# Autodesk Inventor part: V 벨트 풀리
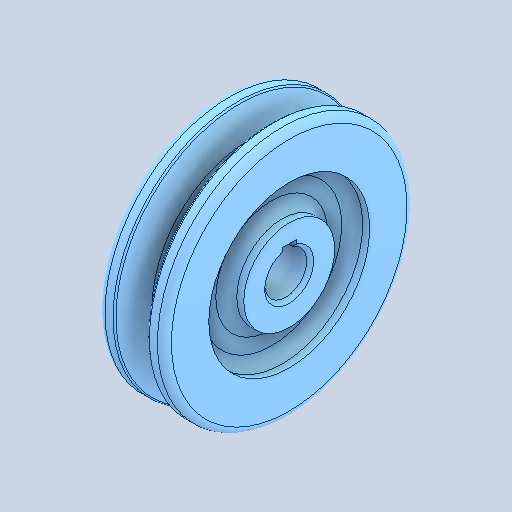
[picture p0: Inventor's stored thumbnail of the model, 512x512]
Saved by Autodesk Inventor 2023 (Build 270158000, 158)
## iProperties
Created: 2026-06
Part Number: V 벨트 풀리
Material: 강철, 주조
Document SubType Name: Modeling
Designer: 4강의실
Density: 7.85 g/cm^3
Appearance: 기본값
Author: jhkim
Sending System: Autodesk Inventor 2027
Preprocessor: ST-DEVELOPER v20.1
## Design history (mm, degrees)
feature "솔리드1"
node "솔리드2"
